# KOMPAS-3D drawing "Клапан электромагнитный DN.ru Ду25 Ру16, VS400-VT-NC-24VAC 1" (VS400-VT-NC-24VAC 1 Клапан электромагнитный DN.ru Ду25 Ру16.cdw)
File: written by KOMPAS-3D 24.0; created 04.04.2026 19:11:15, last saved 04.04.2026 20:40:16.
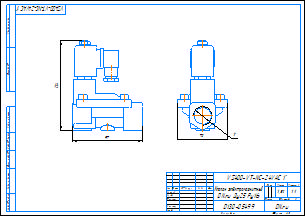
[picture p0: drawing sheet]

Document properties: c3d_UniqueCompID: ef56311e-7521-43dc-8291-0e6108b3d81d; Обозначение: VS400-ET-NC-220VAC 1; Наименование: Клапан электромагнитный DN.ru Ду25 Ру16; Автор: artio; Класс точности: c; Знак неуказанной шероховатости: Шероховатость не задана; Рассекать на разрезах: Да; c3d_UniqueCompID: ef56311e-7521-43dc-8291-0e6108b3d81d; Обозначение: VS400-ET-NC-220VAC 1-2; Наименование: Клапан электромагнитный DN.ru Ду15 Ру16; Автор: artio; Класс точности: c; Знак неуказанной шероховатости: Шероховатость не задана; Рассекать на разрезах: Да; c3d_UniqueCompID: ef56311e-7521-43dc-8291-0e6108b3d81d; Обозначение: VS400-ET-NC-220VAC 3-4; Наименование: Клапан электромагнитный DN.ru Ду20 Ру16; Автор: artio; Класс точности: c; Знак неуказанной шероховатости: Шероховатость не задана; Рассекать на разрезах: Да; c3d_UniqueCompID: ef56311e-7521-43dc-8291-0e6108b3d81d; Обозначение: VS400-ET-NC-220VAC 3-8; Наименование: Клапан электромагнитный DN.ru Ду10 Ру16; Автор: artio; Класс точности: c; Знак неуказанной шероховатости: Шероховатость не задана; Рассекать на разрезах: Да; Автор: artio; Форматы листов документа: A3; Полное имя файла: VS400-VT-NC-24VAC 1 Клапан электромагнитный DN.ru Ду25 Ру16.m3d; Масса: 1.524; Наименование: Клапан электромагнитный DN.ru Ду25 Ру16; Количество листов документа: 1; Примечание: D130-05499

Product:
- Body: Тело 1  | qty 1
    Масса: 1.76797
- Part/product: Клапан электромагнитный DN.ru Ду25 Ру16  | designation VS400-VT-NC-24VAC 1
    Масса: 1.524
    Раздел спецификации: Прочие изделия
    Примечание: D130-05499
    additional columns: ef56311e-7521-43dc-8291-0e6108b3d81d; VS400-ET-NC-220VAC 1; artio; c; Шероховатость не задана; Да

Views: Вид 1, Спереди
Referenced files in C:\Users\artio\OneDrive\Рабочий стол\Клапан электромагнитный DN.ru\VS400-ET-NC\VS400-ET-NC-24VDC\: VS400-ET-NC-24VDC 3-8 Клапан электромагнитный DN.ru Ду10 Ру16.m3d
Referenced files in C:\Users\artio\OneDrive\Рабочий стол\Клапан электромагнитный DN.ru\VS400-VT-NC\VS400-VT-NC-24VAC\: VS400-VT-NC-24VAC 1 Клапан электромагнитный DN.ru Ду25 Ру16.m3d
Referenced files in C:\Users\artio\OneDrive\Рабочий стол\Клапан электромагнитный DN.ru\VS400-ET-NC\: VS400-ET-NC-24VDC 3-8 Клапан электромагнитный DN.ru Ду10 Ру16.cdw
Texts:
  VS400-VT-NC-24VAC 1
  Клапан электромагнитный
  DN.ru Ду25 Ру16
  VS400-VT-NC-24VAC 1"
  VS400-VT-NC-24VAC 1"-
  Клапан электромагнитный DN.ru Ду25 Ру16
  VS400-VT-NC-24VAC 1 Клапан электромагнитный DN.ru Ду25 Ру16
Dimensions and other numbers on the sheet: 0; 3; 2; 4; 70; 1:1; 1; 1,52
